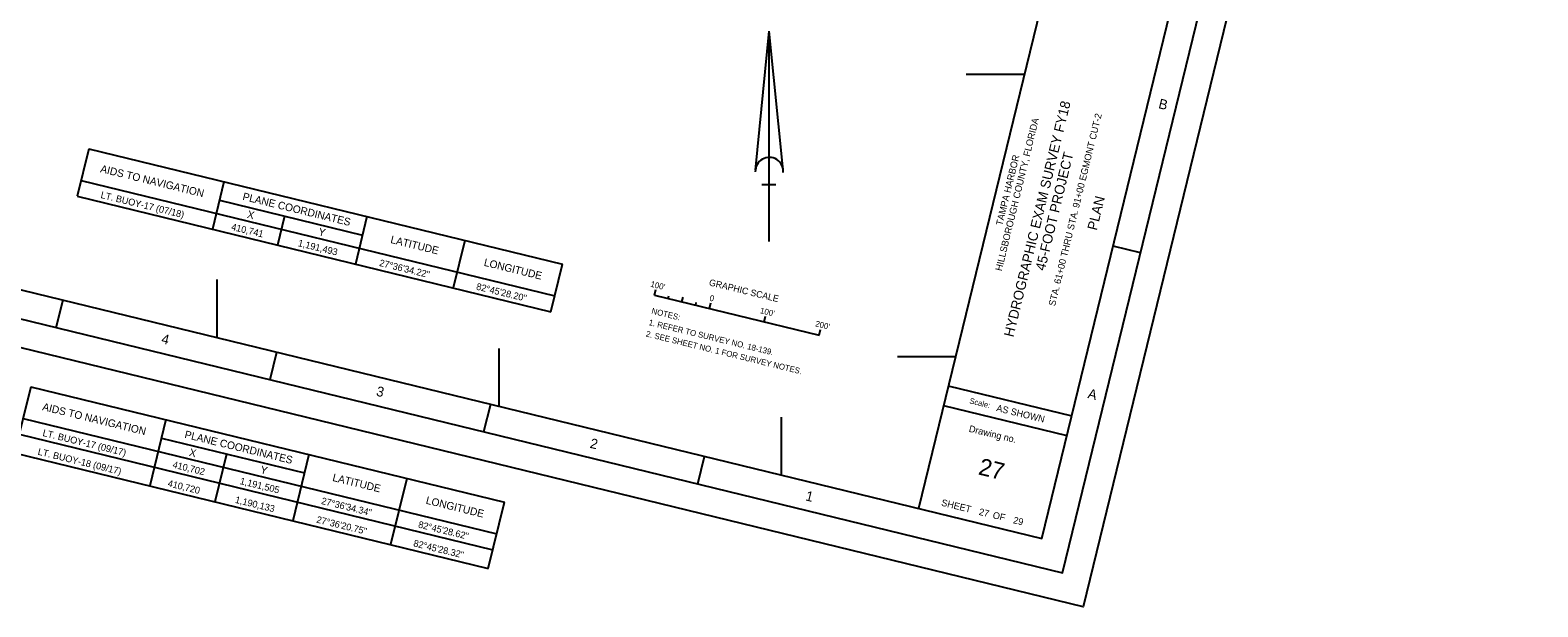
# Model space of a CAD drawing. Extents: x 409260 to 414340, y 1188556 to 1192902.
# Drawn here: x 411669 to 414340, y 1188556 to 1189578 of the extents above; entities that cross this region are included whole.
import ezdxf

# ---------------------------------------------------------------- set-up
doc = ezdxf.new("R2010")
doc.units = 0
for name, color, linetype in [('G-ANNO-NPLT', 7, 'Continuous'), ('G-ANNO-TEXT-DRWG', 7, 'Continuous'), ('G-ANNO-TEXT-PROJ', 7, 'Continuous'), ('G-ANNO-TEXT-TTLB', 7, 'Continuous'), ('G-ANNO-TTLB', 7, 'Continuous'), ('V-ANNO-NOTE', 7, 'Continuous'), ('V-ANNO-SCHD', 7, 'Continuous'), ('V-ANNO-SYMB', 7, 'Continuous'), ('V-TOPO-COOR-STAT', 7, 'Continuous')]:
    doc.layers.add(name, color=color, linetype=linetype)

msp = doc.modelspace()

# ---------------------------------------------------------------- linework, layer by layer
at = {"layer": 'G-ANNO-NPLT'}
msp.add_lwpolyline([(410065.6, 1192901.9), (414340.3, 1191859.4), (413534.7, 1188556.2), (409260, 1189598.7)], close=True, dxfattribs=at)
msp.add_lwpolyline([(413546.6, 1188604.8), (413534.7, 1188556.2), (413486.1, 1188568.1)], dxfattribs=at)
at = {"layer": 'G-ANNO-TTLB'}
for p, q in [((414000.8, 1191839.2), (413242.6, 1188730.4)), ((413636.2, 1189183.3), (413587.6, 1189195.2)), ((411715.2, 1189051.4), (411727.1, 1189100)), ((412094.1, 1188959), (412106, 1189007.6)), ((413295.6, 1188947.8), (413514.3, 1188894.4)), ((412473, 1188866.6), (412484.9, 1188915.2)), ((413287.2, 1188913.1), (413505.8, 1188859.8)), ((412851.9, 1188774.2), (412863.8, 1188822.8))]:
    msp.add_line(p, q, dxfattribs=at)
for points in [[(409320.4, 1189635.4), (413498, 1188616.6), (414279.8, 1191822.7), (410102.3, 1192841.4)], [(414219.4, 1191785.9), (410211.9, 1192763.3), (409453.7, 1189654.4), (413461.3, 1188677.1)]]:
    msp.add_lwpolyline(points, close=True, dxfattribs=at)
at = {"layer": 'V-ANNO-NOTE'}
for p, q in [((412775.2, 1189108.6), (412777.7, 1189118.7)), ((412775.2, 1189108.6), (413066.7, 1189037.5)), ((412799.5, 1189102.7), (412800.6, 1189107.3)), ((412823.8, 1189096.7), (412825.8, 1189105)), ((412848.1, 1189090.8), (412849.2, 1189095.5)), ((412872.3, 1189084.9), (412874.8, 1189095)), ((412872.3, 1189084.9), (412874.8, 1189095)), ((412872.3, 1189084.9), (412873.5, 1189089.7)), ((412969.5, 1189061.2), (412972, 1189071.3)), ((413066.7, 1189037.5), (413069.1, 1189047.6))]:
    msp.add_line(p, q, dxfattribs=at)
at = {"layer": 'V-ANNO-SCHD'}
for p, q in [((411772.7, 1189367.9), (411752.1, 1189283.8)), ((411772.7, 1189367.9), (412612.1, 1189163.2)), ((411759, 1189311.8), (412598.4, 1189107.1)), ((412012.3, 1189309.5), (411991.8, 1189225.4)), ((411752.1, 1189283.8), (412591.6, 1189079.1)), ((412004.3, 1189276.8), (412257.6, 1189215)), ((412119.8, 1189248.6), (412107.3, 1189197.2)), ((412265.6, 1189247.7), (412245.1, 1189163.6)), ((412438.8, 1189205.5), (412418.3, 1189121.3)), ((412591.6, 1189079.1), (412612.1, 1189163.2)), ((411669.8, 1188946.3), (411641.2, 1188828.9)), ((411669.8, 1188946.3), (412509.3, 1188741.6)), ((411656.2, 1188890.2), (412495.6, 1188685.5)), ((411909.5, 1188887.9), (411880.8, 1188770.4)), ((411649.3, 1188862.2), (412488.7, 1188657.5)), ((411901.5, 1188855.1), (412154.8, 1188793.4)), ((411640.7, 1188829), (412480.2, 1188624.3)), ((412017, 1188827), (411996.3, 1188742.3)), ((412162.8, 1188826.1), (412134.1, 1188708.7)), ((412336, 1188783.8), (412307.4, 1188666.4)), ((412480.6, 1188624.2), (412509.3, 1188741.6))]:
    msp.add_line(p, q, dxfattribs=at)
at = {"layer": 'V-ANNO-SYMB'}
for p, q in [((412953.8, 1189330.2), (412978.5, 1189576)), ((412978.5, 1189203.6), (412978.5, 1189576)), ((413003.2, 1189330.2), (412978.5, 1189576)), ((412990.2, 1189304.2), (412965.4, 1189304.2))]:
    msp.add_line(p, q, dxfattribs=at)
msp.add_arc((412978.5, 1189327.8), 24.8, 355.2984, 182.0673, dxfattribs=at)
at = {"layer": 'V-TOPO-COOR-STAT'}
for p, q in [((413327.4, 1189500), (413430.3, 1189500)), ((412000, 1189033.2), (412000, 1189136.1)), ((412500, 1188911.2), (412500, 1189014.2)), ((413205.5, 1189000), (413308.4, 1189000)), ((413000, 1188789.3), (413000, 1188892.2))]:
    msp.add_line(p, q, dxfattribs=at)

# ---------------------------------------------------------------- texts
at = {"layer": 'G-ANNO-TEXT-DRWG'}
for s, height, rotation, p in [('STA. 61+00 THRU STA. 91+00 EGMONT CUT-2', 12, 76.2946, (413484.8, 1189088.3)), ('PLAN', 17.5, 76.2946, (413558.8, 1189222.2)), ('27', 30, 346.2946, (413347.4, 1188791.1)), (' 27          29', 12, 346.2946, (413344.7, 1188720.4))]:
    msp.add_text(s, height=height, rotation=rotation, dxfattribs=at).set_placement(p)
at = {"layer": 'G-ANNO-TEXT-PROJ'}
for s, height, p in [('HYDROGRAPHIC EXAM SURVEY FY18', 17.5, (413410.9, 1189033.1)), ('HILLSBOROUGH COUNTY, FLORIDA', 12, (413390.4, 1189150.4)), ('TAMPA HARBOR', 12, (413391.5, 1189230.8)), ('45-FOOT PROJECT', 17.5, (413466.7, 1189150.8))]:
    msp.add_text(s, height=height, rotation=76.2946, dxfattribs=at).set_placement(p)
at = {"layer": 'G-ANNO-TEXT-TTLB'}
for s, height, p in [('Scale:', 10, (413332.5, 1188916.8)), ('AS SHOWN', 12, (413380, 1188903.2)), ('Drawing no.', 12, (413331.3, 1188866.6)), ('SHEET         OF', 12, (413282.5, 1188735.6))]:
    msp.add_text(s, height=height, rotation=346.2946, dxfattribs=at).set_placement(p)
at = {"layer": 'G-ANNO-TTLB'}
for s, p in [('B', (413666.9, 1189440)), ('4', (411900.2, 1189023.4)), ('3', (412280.9, 1188930.6)), ('A', (413541.6, 1188926.3)), ('2', (412659.6, 1188838.3)), ('1', (413041.5, 1188745.1))]:
    msp.add_text(s, height=17.5, rotation=346.2946, dxfattribs=at).set_placement(p)
at = {"layer": 'V-ANNO-NOTE'}
for s, height, p in [("100'", 10.42, (412767.2, 1189123.6)), ('GRAPHIC SCALE', 11.666, (412870.8, 1189125.9)), ('0', 10.4, (412871.9, 1189098.8)), ('NOTES:', 10.42, (412769, 1189075.9)), ("100'", 10.42, (412961.3, 1189076.7)), ('1. REFER TO SURVEY NO. 18-139.', 10.416, (412764.1, 1189055.6)), ("200'", 10.42, (413059.1, 1189053.4)), ('2. SEE SHEET NO. 1 FOR SURVEY NOTES.', 10.416, (412759.1, 1189035.4))]:
    msp.add_text(s, height=height, rotation=346.2946, dxfattribs=at).set_placement(p)
at = {"layer": 'V-ANNO-SCHD'}
for s, height, p in [('AIDS TO NAVIGATION', 13.471, (411792.3, 1189326.5)), ('PLANE COORDINATES', 13.471, (412044.3, 1189277.4)), ('X', 13.5, (412052.4, 1189245.7)), ('Y', 13.5, (412178.5, 1189215)), ('LATITUDE', 13.47, (412306.4, 1189201.1)), ('LONGITUDE', 13.47, (412471.9, 1189160.7)), ('AIDS TO NAVIGATION', 13.471, (411689.5, 1188904.9)), ('PLANE COORDINATES', 13.471, (411941.5, 1188855.8)), ('X', 13.5, (411949.6, 1188824.1)), ('Y', 13.5, (412075.7, 1188793.4)), ('LATITUDE', 13.47, (412203.6, 1188779.5)), ('LONGITUDE', 13.47, (412369.1, 1188739.1))]:
    msp.add_text(s, height=height, rotation=346.2946, dxfattribs=at).set_placement(p)
at = {"layer": 'V-ANNO-SYMB'}
for s, p in [('LT. BUOY-17 (07/18)', (411792.9, 1189280.8)), ('410,741', (412024.3, 1189224.3)), ('1,191,493', (412142.5, 1189195.5)), ('27%%D36\'34.22"', (412286.6, 1189160.4)), ('82%%D45\'28.20"', (412458.4, 1189118.5)), ('LT. BUOY-17 (09/17)', (411690.1, 1188859.1)), ('LT. BUOY-18 (09/17)', (411681.5, 1188826)), ('410,702', (411920.4, 1188803)), ('1,191,505', (412039.6, 1188773.9)), ('410,720', (411911.8, 1188769.8)), ('1,190,133', (412031.1, 1188740.7)), ('27%%D36\'34.34"', (412183.8, 1188738.7)), ('27%%D36\'20.75"', (412175.2, 1188705.6)), ('82%%D45\'28.62"', (412355.6, 1188696.9)), ('82%%D45\'28.32"', (412347, 1188663.7))]:
    msp.add_text(s, height=12, rotation=346.2946, dxfattribs=at).set_placement(p)

doc.saveas('drawing.dxf')
